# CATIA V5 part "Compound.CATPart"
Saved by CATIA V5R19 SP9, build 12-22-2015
Part number: Compound
Definition: design
Nomenclature: Compound
Source: Unknown
Bounding box of the stored display mesh (mm): x 56 to 66.95, y -43.8 to -30.54, z -17.945 to 3.945
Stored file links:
  Z:\charly_robot\Compound.CATPart
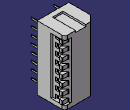
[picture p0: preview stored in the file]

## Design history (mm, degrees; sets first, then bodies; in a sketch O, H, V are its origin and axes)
AxisSystem1: origin (0, 0, 0), X (1, 0, 0), Y (0, 1, 0), Z (0, 0, 1)
Set1
  DatumSurface1 "CLOSED_SHELL #16540"
  DatumSurface2 "CLOSED_SHELL #17448"
  DatumSurface3 "CLOSED_SHELL #18356"
  DatumSurface4 "CLOSED_SHELL #18842"
  DatumSurface5 "CLOSED_SHELL #19750"
  DatumSurface6 "CLOSED_SHELL #20236"
  DatumSurface7 "CLOSED_SHELL #20722"
  DatumSurface8 "CLOSED_SHELL #21208"
  DatumSurface9 "CLOSED_SHELL #21694"
  DatumSurface10 "CLOSED_SHELL #25624"
  DatumSurface11 "CLOSED_SHELL #26110"
  DatumSurface12 "CLOSED_SHELL #26596"
  DatumSurface13 "CLOSED_SHELL #27082"
  DatumSurface14 "CLOSED_SHELL #27568"
  DatumSurface15 "CLOSED_SHELL #28054"
  DatumSurface16 "CLOSED_SHELL #28962"
  DatumSurface17 "CLOSED_SHELL #29448"
  DatumSurface18 "CLOSED_SHELL #29934"
  DatumSurface19 "CLOSED_SHELL #30420"
  DatumSurface20 "CLOSED_SHELL #31328"
  DatumSurface21 "CLOSED_SHELL #32236"
  DatumSurface22 "CLOSED_SHELL #32722"
  DatumSurface23 "CLOSED_SHELL #33630"
  DatumSurface24 "CLOSED_SHELL #34538"
  DatumSurface25 "CLOSED_SHELL #35024"
Body1 (main body)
